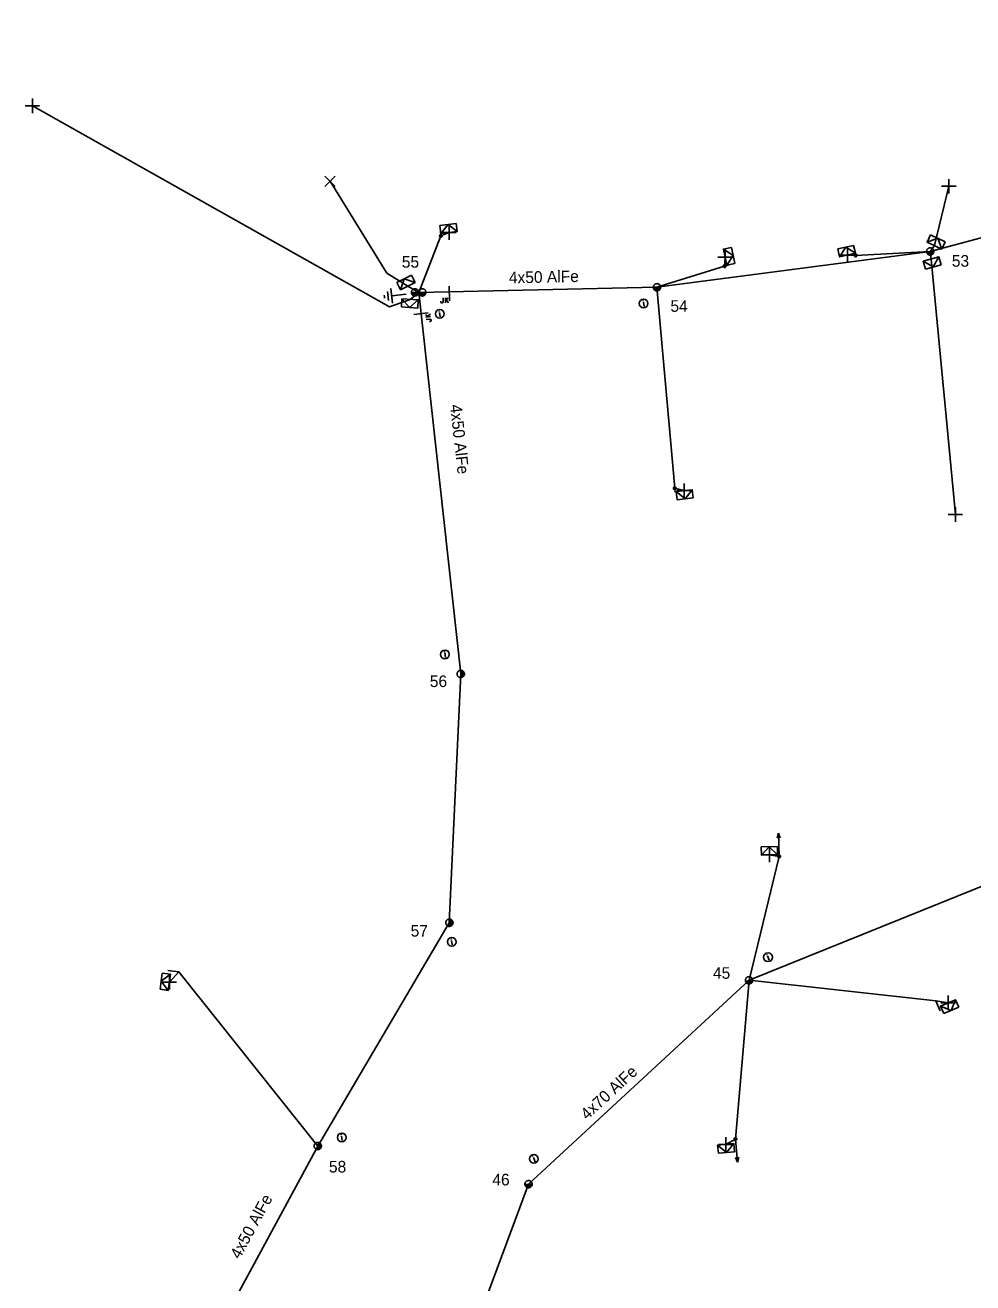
# Model space of a CAD drawing. Extents: x -544780 to -541582, y -1198995 to -1196551.
# Drawn here: x -544642.5 to -544561, y -1198448.1 to -1198340 of the extents above; entities that cross this region are included whole.
import ezdxf

# ---------------------------------------------------------------- set-up
doc = ezdxf.new("R2010")
doc.units = 0
for name, color, linetype in [('Vrstva 1', 7, 'Continuous'), ('Vrstva 10', 7, 'Continuous'), ('Vrstva 13', 7, 'Continuous'), ('Vrstva 14', 7, 'Continuous'), ('Vrstva 15', 7, 'Continuous'), ('Vrstva 18', 7, 'Continuous'), ('Vrstva 2', 7, 'Continuous'), ('Vrstva 31', 7, 'Continuous'), ('Vrstva 34', 7, 'Continuous'), ('Vrstva 36', 7, 'Continuous'), ('Vrstva 54', 7, 'Continuous'), ('Vrstva 59', 7, 'Continuous'), ('Vrstva 8', 7, 'Continuous'), ('Vrstva 9', 7, 'Continuous')]:
    doc.layers.add(name, color=color, linetype=linetype)

# ---------------------------------------------------------------- blocks, each defined once
blk = doc.blocks.new('NN440')
at = {"layer": 'Vrstva 2'}
for points in [[(0.63, 0), (0.63, 0.06), (0.62, 0.13), (0.6, 0.19), (0.58, 0.25), (0.55, 0.31), (0.51, 0.37), (0.47, 0.42), (0.42, 0.46), (0.37, 0.51), (0.32, 0.54), (0.26, 0.57), (0.2, 0.59), (0.13, 0.61), (0.07, 0.62), (0, 0.63), (-0.06, 0.62), (-0.13, 0.61), (-0.19, 0.59), (-0.26, 0.57), (-0.31, 0.54), (-0.37, 0.51), (-0.42, 0.46), (-0.47, 0.42), (-0.51, 0.37), (-0.54, 0.31), (-0.57, 0.25), (-0.6, 0.19), (-0.62, 0.13), (-0.63, 0.06), (-0.63, 0), (-0.63, -0.07), (-0.62, -0.14), (-0.6, -0.2), (-0.57, -0.26), (-0.54, -0.32), (-0.51, -0.37), (-0.47, -0.43), (-0.42, -0.47), (-0.37, -0.51), (-0.31, -0.55), (-0.26, -0.58), (-0.19, -0.6), (-0.13, -0.62), (-0.06, -0.63), (0, -0.63), (0.07, -0.63), (0.13, -0.62), (0.2, -0.6), (0.26, -0.58), (0.32, -0.55), (0.37, -0.51), (0.42, -0.47), (0.47, -0.43), (0.51, -0.37), (0.55, -0.32), (0.58, -0.26), (0.6, -0.2), (0.62, -0.14), (0.63, -0.07), (0.63, 0)], [(-0.63, 0), (0.63, 0)], [(-0.6, -0.18), (0.57, -0.18)], [(-0.51, -0.32), (0.5, -0.32)], [(-0.37, -0.47), (0.35, -0.47)]]:
    blk.add_lwpolyline(points, dxfattribs=at)
blk = doc.blocks.new('NN450')
at = {"layer": 'Vrstva 2'}
for points in [[(0, 0), (0, 0.07), (-0.01, 0.13), (-0.03, 0.19), (-0.05, 0.25), (-0.08, 0.31), (-0.12, 0.37), (-0.16, 0.42), (-0.21, 0.46), (-0.26, 0.51), (-0.31, 0.54), (-0.37, 0.57), (-0.43, 0.59), (-0.5, 0.61), (-0.56, 0.62), (-0.63, 0.62), (-0.69, 0.62), (-0.75, 0.61), (-0.82, 0.59), (-0.88, 0.57), (-0.94, 0.54), (-0.99, 0.51), (-1.04, 0.46), (-1.09, 0.42), (-1.13, 0.37), (-1.17, 0.31), (-1.2, 0.25), (-1.22, 0.19), (-1.24, 0.13), (-1.25, 0.07), (-1.25, 0), (-1.25, -0.07), (-1.24, -0.13), (-1.22, -0.19), (-1.2, -0.25), (-1.17, -0.31), (-1.13, -0.37), (-1.09, -0.42), (-1.04, -0.46), (-0.99, -0.51), (-0.94, -0.54), (-0.88, -0.57), (-0.82, -0.59), (-0.75, -0.61), (-0.69, -0.62), (-0.62, -0.63), (-0.56, -0.62), (-0.5, -0.61), (-0.43, -0.59), (-0.37, -0.57), (-0.31, -0.54), (-0.26, -0.51), (-0.21, -0.46), (-0.16, -0.42), (-0.12, -0.37), (-0.08, -0.31), (-0.05, -0.25), (-0.03, -0.19), (-0.01, -0.13), (0, -0.07), (0, 0)], [(1.25, 0), (1.25, 0.07), (1.24, 0.13), (1.22, 0.19), (1.2, 0.25), (1.17, 0.31), (1.13, 0.37), (1.09, 0.42), (1.04, 0.46), (0.99, 0.51), (0.94, 0.54), (0.88, 0.57), (0.82, 0.59), (0.75, 0.61), (0.69, 0.62), (0.62, 0.62), (0.56, 0.62), (0.5, 0.61), (0.43, 0.59), (0.37, 0.57), (0.31, 0.54), (0.26, 0.51), (0.21, 0.46), (0.16, 0.42), (0.12, 0.37), (0.08, 0.31), (0.05, 0.25), (0.03, 0.19), (0.01, 0.13), (0, 0.07), (0, 0), (0, -0.07), (0.01, -0.13), (0.03, -0.19), (0.05, -0.25), (0.08, -0.31), (0.12, -0.37), (0.16, -0.42), (0.21, -0.46), (0.26, -0.51), (0.31, -0.54), (0.37, -0.57), (0.43, -0.59), (0.5, -0.61), (0.56, -0.62), (0.63, -0.63), (0.69, -0.62), (0.75, -0.61), (0.82, -0.59), (0.88, -0.57), (0.94, -0.54), (0.99, -0.51), (1.04, -0.46), (1.09, -0.42), (1.13, -0.37), (1.17, -0.31), (1.2, -0.25), (1.22, -0.19), (1.24, -0.13), (1.25, -0.07), (1.25, 0)], [(-1.25, 0), (1.25, 0)], [(-1.23, -0.16), (-0.02, -0.16)], [(-1.16, -0.32), (-0.09, -0.32)], [(-1.03, -0.47), (-0.22, -0.47)], [(0.02, -0.16), (1.23, -0.16)], [(0.09, -0.32), (1.16, -0.32)], [(0.22, -0.47), (1.03, -0.47)]]:
    blk.add_lwpolyline(points, dxfattribs=at)
blk = doc.blocks.new('NN560')
at = {"layer": 'Vrstva 2'}
for points in [[(2, 0), (1.59, 0.14)], [(0, 0), (2, 0)], [(2, 0), (1.59, -0.13)]]:
    blk.add_lwpolyline(points, dxfattribs=at)
blk = doc.blocks.new('NN840')
at = {"layer": 'Vrstva 15'}
for points in [[(0, 0.62), (0, -0.63)], [(-0.75, -0.71), (-0.75, -0.66)], [(-0.73, -0.76), (-0.75, -0.71)], [(-0.66, -0.8), (-0.73, -0.76)], [(-0.63, -0.8), (-0.66, -0.8)], [(-0.56, -0.76), (-0.63, -0.8)], [(-0.54, -0.71), (-0.56, -0.76)], [(-0.54, -0.38), (-0.54, -0.71)], [(-0.33, -0.38), (-0.33, -0.8)], [(-0.33, -0.64), (-0.13, -0.38)], [(-0.26, -0.56), (-0.09, -0.8)]]:
    blk.add_lwpolyline(points, dxfattribs=at)
blk = doc.blocks.new('NN770')
at = {"layer": 'Vrstva 10'}
for p, q in [((0, 0.19), (0, 0.26)), ((0, -0.28), (0, 0.11))]:
    blk.add_line(p, q, dxfattribs=at)
blk.add_circle((0, -0.01), 0.375, dxfattribs=at)
blk = doc.blocks.new('NN800')
at = {"layer": 'Vrstva 1'}
for points in [[(-0.44, 0.44), (0.44, -0.44)], [(-0.44, -0.44), (0.44, 0.44)]]:
    blk.add_lwpolyline(points, dxfattribs=at)
blk = doc.blocks.new('NN630')
at = {"layer": 'Vrstva 9'}
for points in [[(0, -0.7), (-0.7, 0)], [(-0.7, -0.7), (-0.7, 0), (0.7, 0), (0.7, -0.7)], [(-0.7, -0.7), (0.7, -0.7)], [(0, -0.7), (0.7, 0)]]:
    blk.add_lwpolyline(points, dxfattribs=at)
blk = doc.blocks.new('NN810')
at = {"layer": 'Vrstva 14'}
for points in [[(0, -0.64), (0, -1.89)], [(0.63, -1.89), (-0.62, -1.89)], [(0.39, -2.2), (-0.4, -2.2)], [(0, -2.52), (-0.12, -2.52)], [(0.14, -2.52), (0, -2.52)]]:
    blk.add_lwpolyline(points, dxfattribs=at)
blk = doc.blocks.new('NN500')
at = {"layer": 'Vrstva 2'}
for points in [[(0, -0.24), (0.02, -0.23), (0.05, -0.23), (0.07, -0.22), (0.09, -0.22), (0.12, -0.2), (0.14, -0.19), (0.16, -0.18), (0.17, -0.16), (0.19, -0.14), (0.2, -0.12), (0.21, -0.1), (0.22, -0.07), (0.23, -0.05), (0.23, -0.02), (0.23, 0), (0.23, 0.02), (0.23, 0.05), (0.22, 0.07), (0.21, 0.1), (0.2, 0.12), (0.19, 0.14), (0.17, 0.16), (0.16, 0.17), (0.14, 0.19), (0.12, 0.2), (0.09, 0.21), (0.07, 0.22), (0.05, 0.23), (0.02, 0.23), (0, 0.23), (-0.03, 0.23), (-0.05, 0.23), (-0.07, 0.22), (-0.1, 0.21), (-0.12, 0.2), (-0.14, 0.19), (-0.16, 0.17), (-0.18, 0.16), (-0.19, 0.14), (-0.2, 0.12), (-0.22, 0.1), (-0.22, 0.07), (-0.23, 0.05), (-0.23, 0.02), (-0.24, 0), (-0.23, -0.02), (-0.23, -0.05), (-0.22, -0.07), (-0.22, -0.1), (-0.2, -0.12), (-0.19, -0.14), (-0.18, -0.16), (-0.16, -0.18), (-0.14, -0.19), (-0.12, -0.2), (-0.1, -0.22), (-0.07, -0.22), (-0.05, -0.23), (-0.03, -0.23), (0, -0.24)], [(0, -0.24), (0.02, -0.23), (0.05, -0.23), (0.07, -0.22), (0.09, -0.22), (0.12, -0.2), (0.14, -0.19), (0.16, -0.18), (0.17, -0.16), (0.19, -0.14), (0.2, -0.12), (0.21, -0.1), (0.22, -0.07), (0.23, -0.05), (0.23, -0.02), (0.23, 0), (0.23, 0.02), (0.23, 0.05), (0.22, 0.07), (0.21, 0.1), (0.2, 0.12), (0.19, 0.14), (0.17, 0.16), (0.16, 0.17), (0.14, 0.19), (0.12, 0.2), (0.09, 0.21), (0.07, 0.22), (0.05, 0.23), (0.02, 0.23), (0, 0.23), (-0.03, 0.23), (-0.05, 0.23), (-0.07, 0.22), (-0.1, 0.21), (-0.12, 0.2), (-0.14, 0.19), (-0.16, 0.17), (-0.18, 0.16), (-0.19, 0.14), (-0.2, 0.12), (-0.22, 0.1), (-0.22, 0.07), (-0.23, 0.05), (-0.23, 0.02), (-0.24, 0), (-0.23, -0.02), (-0.23, -0.05), (-0.22, -0.07), (-0.22, -0.1), (-0.2, -0.12), (-0.19, -0.14), (-0.18, -0.16), (-0.16, -0.18), (-0.14, -0.19), (-0.12, -0.2), (-0.1, -0.22), (-0.07, -0.22), (-0.05, -0.23), (-0.03, -0.23), (0, -0.24)], [(0, -0.21), (0.02, -0.2), (0.04, -0.2), (0.06, -0.2), (0.08, -0.19), (0.1, -0.18), (0.12, -0.17), (0.14, -0.15), (0.15, -0.14), (0.16, -0.12), (0.18, -0.1), (0.19, -0.08), (0.19, -0.06), (0.2, -0.04), (0.2, -0.02), (0.2, 0), (0.2, 0.02), (0.2, 0.04), (0.19, 0.06), (0.19, 0.08), (0.18, 0.1), (0.16, 0.12), (0.15, 0.14), (0.14, 0.15), (0.12, 0.17), (0.1, 0.18), (0.08, 0.19), (0.06, 0.19), (0.04, 0.2), (0.02, 0.2), (0, 0.2), (-0.02, 0.2), (-0.04, 0.2), (-0.06, 0.19), (-0.08, 0.19), (-0.1, 0.18), (-0.12, 0.17), (-0.14, 0.15), (-0.15, 0.14), (-0.17, 0.12), (-0.18, 0.1), (-0.19, 0.08), (-0.2, 0.06), (-0.2, 0.04), (-0.21, 0.02), (-0.21, 0), (-0.21, -0.02), (-0.2, -0.04), (-0.2, -0.06), (-0.19, -0.08), (-0.18, -0.1), (-0.17, -0.12), (-0.15, -0.14), (-0.14, -0.15), (-0.12, -0.17), (-0.1, -0.18), (-0.08, -0.19), (-0.06, -0.2), (-0.04, -0.2), (-0.02, -0.2), (0, -0.21)], [(0, -0.18), (0.02, -0.18), (0.04, -0.17), (0.05, -0.17), (0.07, -0.16), (0.09, -0.15), (0.1, -0.14), (0.12, -0.13), (0.13, -0.12), (0.14, -0.1), (0.15, -0.09), (0.16, -0.07), (0.17, -0.05), (0.17, -0.04), (0.17, -0.02), (0.17, 0), (0.17, 0.02), (0.17, 0.04), (0.17, 0.05), (0.16, 0.07), (0.15, 0.09), (0.14, 0.1), (0.13, 0.12), (0.12, 0.13), (0.1, 0.14), (0.09, 0.15), (0.07, 0.16), (0.05, 0.17), (0.04, 0.17), (0.02, 0.17), (0, 0.18), (-0.02, 0.17), (-0.04, 0.17), (-0.06, 0.17), (-0.07, 0.16), (-0.09, 0.15), (-0.1, 0.14), (-0.12, 0.13), (-0.13, 0.12), (-0.14, 0.1), (-0.15, 0.09), (-0.16, 0.07), (-0.17, 0.05), (-0.17, 0.04), (-0.18, 0.02), (-0.18, 0), (-0.18, -0.02), (-0.17, -0.04), (-0.17, -0.05), (-0.16, -0.07), (-0.15, -0.09), (-0.14, -0.1), (-0.13, -0.12), (-0.12, -0.13), (-0.1, -0.14), (-0.09, -0.15), (-0.07, -0.16), (-0.06, -0.17), (-0.04, -0.17), (-0.02, -0.18), (0, -0.18)], [(0, -0.15), (0.01, -0.15), (0.03, -0.14), (0.04, -0.14), (0.06, -0.13), (0.07, -0.13), (0.08, -0.12), (0.1, -0.11), (0.11, -0.1), (0.12, -0.09), (0.13, -0.07), (0.13, -0.06), (0.14, -0.05), (0.14, -0.03), (0.14, -0.02), (0.14, 0), (0.14, 0.01), (0.14, 0.03), (0.14, 0.04), (0.13, 0.06), (0.13, 0.07), (0.12, 0.09), (0.11, 0.1), (0.1, 0.11), (0.08, 0.12), (0.07, 0.13), (0.06, 0.13), (0.04, 0.14), (0.03, 0.14), (0.01, 0.14), (0, 0.15), (-0.02, 0.14), (-0.03, 0.14), (-0.05, 0.14), (-0.06, 0.13), (-0.07, 0.13), (-0.09, 0.12), (-0.1, 0.11), (-0.11, 0.1), (-0.12, 0.09), (-0.13, 0.07), (-0.13, 0.06), (-0.14, 0.04), (-0.14, 0.03), (-0.15, 0.01), (-0.15, 0), (-0.15, -0.02), (-0.14, -0.03), (-0.14, -0.05), (-0.13, -0.06), (-0.13, -0.07), (-0.12, -0.09), (-0.11, -0.1), (-0.1, -0.11), (-0.09, -0.12), (-0.07, -0.13), (-0.06, -0.13), (-0.05, -0.14), (-0.03, -0.14), (-0.02, -0.15), (0, -0.15)], [(0, -0.12), (0.01, -0.12), (0.02, -0.11), (0.03, -0.11), (0.05, -0.11), (0.06, -0.1), (0.07, -0.09), (0.08, -0.09), (0.09, -0.08), (0.09, -0.07), (0.1, -0.06), (0.11, -0.05), (0.11, -0.04), (0.11, -0.02), (0.11, -0.01), (0.12, 0), (0.11, 0.01), (0.11, 0.02), (0.11, 0.04), (0.11, 0.05), (0.1, 0.06), (0.09, 0.07), (0.09, 0.08), (0.08, 0.09), (0.07, 0.09), (0.06, 0.1), (0.05, 0.11), (0.03, 0.11), (0.02, 0.11), (0.01, 0.12), (0, 0.12), (-0.01, 0.12), (-0.03, 0.11), (-0.04, 0.11), (-0.05, 0.11), (-0.06, 0.1), (-0.07, 0.09), (-0.08, 0.09), (-0.09, 0.08), (-0.1, 0.07), (-0.1, 0.06), (-0.11, 0.05), (-0.11, 0.04), (-0.12, 0.02), (-0.12, 0.01), (-0.12, 0), (-0.12, -0.01), (-0.12, -0.02), (-0.11, -0.04), (-0.11, -0.05), (-0.1, -0.06), (-0.1, -0.07), (-0.09, -0.08), (-0.08, -0.09), (-0.07, -0.09), (-0.06, -0.1), (-0.05, -0.11), (-0.04, -0.11), (-0.03, -0.11), (-0.01, -0.12), (0, -0.12)], [(0, -0.09), (0.01, -0.09), (0.02, -0.09), (0.03, -0.08), (0.03, -0.08), (0.04, -0.08), (0.05, -0.07), (0.06, -0.07), (0.06, -0.06), (0.07, -0.05), (0.07, -0.04), (0.08, -0.04), (0.08, -0.03), (0.08, -0.02), (0.09, -0.01), (0.09, 0), (0.09, 0.01), (0.08, 0.02), (0.08, 0.03), (0.08, 0.03), (0.07, 0.04), (0.07, 0.05), (0.06, 0.06), (0.06, 0.06), (0.05, 0.07), (0.04, 0.07), (0.03, 0.08), (0.03, 0.08), (0.02, 0.08), (0.01, 0.09), (0, 0.09), (-0.01, 0.09), (-0.02, 0.08), (-0.03, 0.08), (-0.04, 0.08), (-0.04, 0.07), (-0.05, 0.07), (-0.06, 0.06), (-0.07, 0.06), (-0.07, 0.05), (-0.08, 0.04), (-0.08, 0.03), (-0.08, 0.03), (-0.09, 0.02), (-0.09, 0.01), (-0.09, 0), (-0.09, -0.01), (-0.09, -0.02), (-0.08, -0.03), (-0.08, -0.04), (-0.08, -0.04), (-0.07, -0.05), (-0.07, -0.06), (-0.06, -0.07), (-0.05, -0.07), (-0.04, -0.08), (-0.04, -0.08), (-0.03, -0.08), (-0.02, -0.09), (-0.01, -0.09), (0, -0.09)], [(0, -0.06), (0, -0.06), (0.01, -0.06), (0.02, -0.05), (0.02, -0.05), (0.03, -0.05), (0.03, -0.05), (0.04, -0.04), (0.04, -0.04), (0.05, -0.03), (0.05, -0.03), (0.05, -0.02), (0.05, -0.02), (0.05, -0.01), (0.06, -0.01), (0.06, 0), (0.06, 0.01), (0.05, 0.01), (0.05, 0.02), (0.05, 0.02), (0.05, 0.03), (0.05, 0.03), (0.04, 0.04), (0.04, 0.04), (0.03, 0.05), (0.03, 0.05), (0.02, 0.05), (0.02, 0.05), (0.01, 0.06), (0, 0.06), (0, 0.06), (-0.01, 0.06), (-0.01, 0.06), (-0.02, 0.05), (-0.02, 0.05), (-0.03, 0.05), (-0.03, 0.05), (-0.04, 0.04), (-0.04, 0.04), (-0.05, 0.03), (-0.05, 0.03), (-0.05, 0.02), (-0.06, 0.02), (-0.06, 0.01), (-0.06, 0.01), (-0.06, 0), (-0.06, -0.01), (-0.06, -0.01), (-0.06, -0.02), (-0.05, -0.02), (-0.05, -0.03), (-0.05, -0.03), (-0.04, -0.04), (-0.04, -0.04), (-0.03, -0.05), (-0.03, -0.05), (-0.02, -0.05), (-0.02, -0.05), (-0.01, -0.06), (-0.01, -0.06), (0, -0.06)], [(0, -0.03), (0, -0.03), (0, -0.03), (0.01, -0.03), (0.01, -0.03), (0.01, -0.02), (0.02, -0.02), (0.02, -0.02), (0.02, -0.02), (0.02, -0.02), (0.02, -0.01), (0.02, -0.01), (0.03, -0.01), (0.03, -0.01), (0.03, 0), (0.03, 0), (0.03, 0), (0.03, 0.01), (0.03, 0.01), (0.02, 0.01), (0.02, 0.01), (0.02, 0.02), (0.02, 0.02), (0.02, 0.02), (0.02, 0.02), (0.01, 0.02), (0.01, 0.02), (0.01, 0.03), (0, 0.03), (0, 0.03), (0, 0.03), (0, 0.03), (-0.01, 0.03), (-0.01, 0.03), (-0.01, 0.02), (-0.02, 0.02), (-0.02, 0.02), (-0.02, 0.02), (-0.02, 0.02), (-0.02, 0.02), (-0.03, 0.01), (-0.03, 0.01), (-0.03, 0.01), (-0.03, 0.01), (-0.03, 0), (-0.03, 0), (-0.03, 0), (-0.03, -0.01), (-0.03, -0.01), (-0.03, -0.01), (-0.03, -0.01), (-0.02, -0.02), (-0.02, -0.02), (-0.02, -0.02), (-0.02, -0.02), (-0.02, -0.02), (-0.01, -0.03), (-0.01, -0.03), (-0.01, -0.03), (0, -0.03), (0, -0.03)], [(0.23, 0), (0.7, 0)]]:
    blk.add_lwpolyline(points, dxfattribs=at)
blk = doc.blocks.new('NN510')
at = {"layer": 'Vrstva 2'}
blk.add_lwpolyline([(0, 0), (0, 0.94)], dxfattribs=at)

msp = doc.modelspace()

# ---------------------------------------------------------------- linework, layer by layer
at = {"layer": 'Vrstva 1'}
for points in [[(-544497.26, -1198339.99), (-544515.91, -1198344.94), (-544540.08, -1198352.85), (-544564.65, -1198359.45), (-544588.16, -1198362.53), (-544608.66, -1198362.97), (-544605.04, -1198395.78), (-544606.03, -1198417.18), (-544617.34, -1198436.38), (-544630.53, -1198460.75)], [(-544486.06, -1198382.39), (-544516.16, -1198395.36), (-544547.54, -1198408.94), (-544580.24, -1198422.13), (-544599.21, -1198439.67), (-544606.56, -1198459.4)]]:
    msp.add_lwpolyline(points, dxfattribs=at)
at = {"layer": 'Vrstva 54'}
for points in [[(-544588.16, -1198362.53), (-544582.34, -1198360.71), (-544582.3, -1198359.93)], [(-544564.65, -1198359.45), (-544571.07, -1198359.79), (-544571.77, -1198359.76)], [(-544608.66, -1198362.97), (-544609.59, -1198362.43)], [(-544608.66, -1198362.97), (-544609.4, -1198363.57)], [(-544588.16, -1198362.53), (-544586.63, -1198379.81), (-544585.82, -1198380.02)], [(-544617.34, -1198436.38), (-544629.3, -1198421.4), (-544630.11, -1198422.3)], [(-544580.24, -1198422.13), (-544581.41, -1198435.78), (-544582.24, -1198436.24)], [(-544580.24, -1198422.13), (-544564.16, -1198423.89), (-544563.11, -1198424.07)]]:
    msp.add_lwpolyline(points, dxfattribs=at)
at = {"layer": 'Vrstva 59'}
for points in [[(-544609.4, -1198363.57), (-544611.17, -1198364.21), (-544641.89, -1198346.93)], [(-544609.59, -1198362.43), (-544611.4, -1198361.31), (-544616.28, -1198353.41)], [(-544564.65, -1198359.45), (-544564.29, -1198358.95), (-544563.05, -1198353.84)], [(-544564.65, -1198359.45), (-544564.58, -1198360.11), (-544562.49, -1198382.08)]]:
    msp.add_lwpolyline(points, dxfattribs=at)
at = {"layer": 'Vrstva 8'}
for points in [[(-544608.66, -1198362.97), (-544606.75, -1198358.1), (-544606.05, -1198357.82)], [(-544580.24, -1198422.13), (-544577.65, -1198411.47), (-544578.48, -1198411.35)]]:
    msp.add_lwpolyline(points, dxfattribs=at)

# ---------------------------------------------------------------- block references
at = {"layer": 'Vrstva 13'}
for name, p, xscale, yscale, rotation in [('NN500', (-544606.75, -1198358.1), 0.49999999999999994, 0.5000000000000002, 97.00900002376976), ('NN500', (-544571.07, -1198359.79), 0.5, 0.5, 102.61700002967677), ('NN440', (-544564.65, -1198359.45), 0.5000000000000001, 0.5, 15.587158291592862), ('NN500', (-544582.34, -1198360.71), 0.5, 0.5, 11.558999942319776), ('NN450', (-544608.66, -1198362.97), 0.49999999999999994, 0.5, -0.36821953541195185), ('NN440', (-544588.16, -1198362.53), 0.5000000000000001, 0.5, 0.1069610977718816), ('NN500', (-544586.63, -1198379.81), 0.49999999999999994, 0.4999999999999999, -83.23899992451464), ('NN440', (-544605.04, -1198395.78), 0.5000000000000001, 0.5, 84.35804726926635), ('NN500', (-544577.65, -1198411.47), 0.5, 0.5, 91.2069999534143), ('NN440', (-544606.02, -1198417.18), 0.49999999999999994, 0.4999999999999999, 84.63436952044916), ('NN440', (-544580.24, -1198422.13), 0.5, 0.5000000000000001, 24.00368600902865), ('NN500', (-544581.41, -1198435.78), 0.5, 0.5000000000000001, -84.63100002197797), ('NN440', (-544617.34, -1198436.38), 0.5000000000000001, 0.5, 80.1898527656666), ('NN440', (-544599.21, -1198439.66), 0.5000000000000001, 0.5, 5.100750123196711)]:
    msp.add_blockref(name, p, dxfattribs=dict(at, xscale=xscale, yscale=yscale, rotation=rotation))
for name, p, rotation in [('NN560', (-544577.65, -1198411.47), 91.20720278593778), ('NN510', (-544629.3, -1198421.4), 82.52778330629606), ('NN510', (-544564.16, -1198423.89), -156.85329162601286), ('NN560', (-544581.41, -1198435.78), -84.63134442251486)]:
    msp.add_blockref(name, p, dxfattribs=dict(at, rotation=rotation))
at = {"layer": 'Vrstva 15', "rotation": -83.69622219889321}
msp.add_blockref('NN810', (-544609.1, -1198363.05), dxfattribs=at)
at = {"layer": 'Vrstva 18'}
for p, rotation in [((-544606.03, -1198363.06), 1.2267193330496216), ((-544608.46, -1198364.81), 96.3037778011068)]:
    msp.add_blockref('NN840', p, dxfattribs=dict(at, rotation=rotation))
at = {"layer": 'Vrstva 31'}
for p, rotation in [((-544606.05, -1198357.82), -172.9913554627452), ((-544564.29, -1198358.95), 154.835924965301), ((-544582.3, -1198359.93), 101.55936663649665), ((-544571.77, -1198359.76), -167.38345009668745), ((-544564.58, -1198360.11), 15.587158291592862), ((-544609.59, -1198362.43), -152.94420464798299), ((-544609.4, -1198363.57), -3.592329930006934), ((-544585.82, -1198380.02), 6.760555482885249), ((-544578.48, -1198411.35), -178.79279714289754), ((-544630.11, -1198422.3), -97.47221667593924), ((-544563.11, -1198424.07), 23.146708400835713), ((-544582.24, -1198436.24), 5.3686554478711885)]:
    msp.add_blockref('NN630', p, dxfattribs=dict(at, rotation=rotation))
at = {"layer": 'Vrstva 34'}
for p, rotation in [((-544641.89, -1198346.93), 45), ((-544563.05, -1198353.84), 45), ((-544606.05, -1198357.82), 45), ((-544582.3, -1198359.93), 45), ((-544571.77, -1198359.76), 45), ((-544585.82, -1198380.02), 45), ((-544562.49, -1198382.08), 44.99999995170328), ((-544578.48, -1198411.35), 45), ((-544630.11, -1198422.3), 45), ((-544563.11, -1198424.07), 45), ((-544582.24, -1198436.24), 45)]:
    msp.add_blockref('NN800', p, dxfattribs=dict(at, rotation=rotation))
msp.add_blockref('NN800', (-544616.28, -1198353.41), dxfattribs=at)
at = {"layer": 'Vrstva 36'}
for p, rotation in [((-544589.31, -1198363.91), 8.038660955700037), ((-544606.85, -1198364.8), 8.038661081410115), ((-544606.4, -1198394.09), 8.038660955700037), ((-544605.82, -1198418.81), 8.03866094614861), ((-544578.61, -1198420.14), 23.313113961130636), ((-544615.28, -1198435.63), 8.03866094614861), ((-544598.75, -1198437.47), 23.313113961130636)]:
    msp.add_blockref('NN770', p, dxfattribs=dict(at, rotation=rotation))

# ---------------------------------------------------------------- texts
at = {"layer": 'Vrstva 14'}
for s, p in [('55', (-544610.11, -1198360.84)), ('53', (-544562.79, -1198360.76)), ('54', (-544587, -1198364.64)), ('56', (-544607.7, -1198396.91)), ('57', (-544609.35, -1198418.37)), ('45', (-544583.34, -1198422)), ('58', (-544616.38, -1198438.66)), ('46', (-544602.32, -1198439.77))]:
    msp.add_text(s, height=1, dxfattribs=at).set_placement(p)
at = {"layer": 'Vrstva 2'}
for s, rotation, p in [('4x50 AlFe', 1.227, (-544600.89, -1198362.2)), ('4x50 AlFe', 276.304, (-544605.96, -1198372.66)), ('4x70 AlFe', 42.74, (-544594.17, -1198434.19)), ('4x50 AlFe', 61.589, (-544624.06, -1198446.17))]:
    msp.add_text(s, height=1, rotation=rotation, dxfattribs=at).set_placement(p)

doc.saveas('drawing.dxf')
